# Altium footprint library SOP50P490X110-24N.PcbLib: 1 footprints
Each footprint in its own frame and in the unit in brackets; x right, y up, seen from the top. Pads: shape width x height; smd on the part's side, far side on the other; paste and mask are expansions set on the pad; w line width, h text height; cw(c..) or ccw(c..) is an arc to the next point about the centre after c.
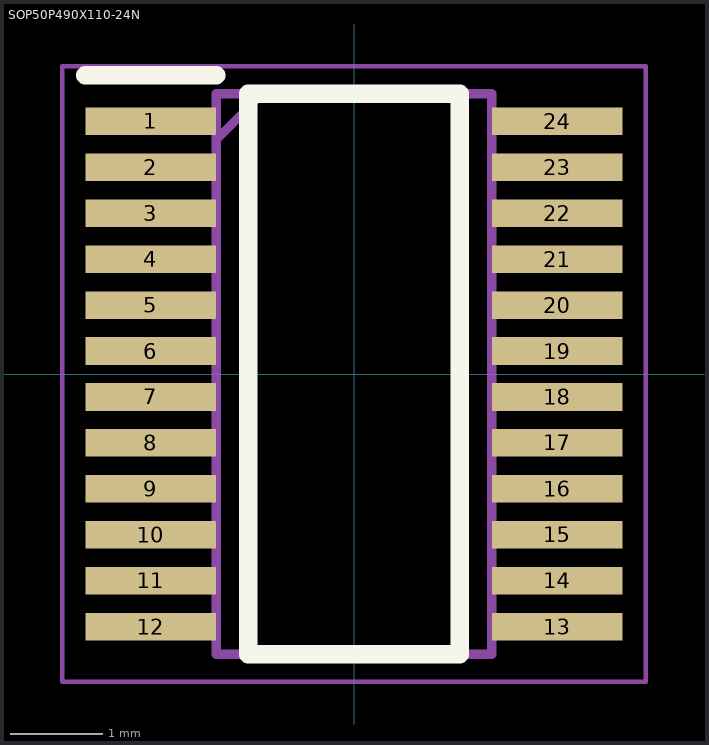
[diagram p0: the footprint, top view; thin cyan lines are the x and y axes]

## SOP50P490X110-24N [mm]
pads (24):
  rect 1.425x0.3 smd: 1(-2.212,2.75) 2(-2.212,2.25) 3(-2.212,1.75) 4(-2.212,1.25) 5(-2.212,0.75) 6(-2.212,0.25) 7(-2.212,-0.25) 8(-2.212,-0.75) 9(-2.212,-1.25) 10(-2.212,-1.75) 11(-2.212,-2.25) 12(-2.212,-2.75) 13(2.212,-2.75) 14(2.212,-2.25) 15(2.212,-1.75) 16(2.212,-1.25) 17(2.212,-0.75) 18(2.212,-0.25) 19(2.212,0.25) 20(2.212,0.75) 21(2.212,1.25) 22(2.212,1.75) 23(2.212,2.25) 24(2.212,2.75)
Top Overlay:
  lines w0.2: -2.925,3.25 -1.5,3.25 ; -1.15,-3.05 1.15,-3.05 1.15,3.05 -1.15,3.05 -1.15,-3.05
Mechanical 15:
  lines w0.1: -1.5,2.55 -1,3.05 ; -1.5,-3.05 1.5,-3.05 1.5,3.05 -1.5,3.05 -1.5,-3.05
Mechanical 20:
  lines w0.05: -3.175,-3.35 3.175,-3.35 3.175,3.35 -3.175,3.35 -3.175,-3.35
